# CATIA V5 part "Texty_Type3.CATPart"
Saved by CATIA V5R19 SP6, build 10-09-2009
Part number: Texty Type3
Bounding box of the stored display mesh (mm): x -20 to 20, y 0 to 0, z -20.085 to 5.085
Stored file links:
  C:\DURATEC\Texty_Type3.CATPart
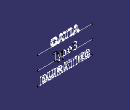
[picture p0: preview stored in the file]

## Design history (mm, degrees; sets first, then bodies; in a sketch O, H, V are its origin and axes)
Parameters
  Text.1 = "CATIA"
  Text.2 = "Type3"
  Text.3 = "DURATEC"
Set1 "Text.1"
  Line1: type PtDir, RefPoint {point type Coord, X 0, Y 0, Z 0}, Direction (1, 0, 0), Start -20, End 20
  TY3TextWarpObject1: Text "CATIA" {= Text.1}, BaseCurve Line1, Circle Start Angle 0, BasePlane zx-plane, Reference Circle Radius 0, Circle Radius 10, ParaGrapheStyleUpgraded "Center", JustificationModeUpgraded false, ParaGraphOffsetStyleUpgraded "Above the baseline", PlaneInversionUpgraded false, SlideCaliper false, ReferenceAxis "0y", CurveInversionUpgraded true, ConvergenceType "Standard", CurveType "Curve", FullTreeVisualization false, Font Type "Arial Rounded MT Bold", Font Type "Arial Rounded MT Bold", Font Type "Arial Rounded MT Bold", Font Type "Arial Rounded MT Bold", Font Type "Arial Rounded MT Bold", Font Type "Arial Rounded MT Bold", Font Family "True type font", Font Family "True type font", Font Family "True type font", Font Family "True type font", Font Family "True type font", Font Family "True type font", Case "None", Case "None", Case "None", Case "None", Case "None", Case "None", Kerning "KERN_STD", Kerning "KERN_STD", Kerning "KERN_STD", Kerning "KERN_STD", Kerning "KERN_STD", Kerning "KERN_STD", Superscript/Subscript "None", Superscript/Subscript "None", Superscript/Subscript "None", Superscript/Subscript "None", Superscript/Subscript "None", Superscript/Subscript "None", Rotation 0, Rotation 0, Rotation 0, Rotation 0, Rotation 0, Rotation 0, Extra Space 0, Extra Space 0, Extra Space 0, Extra Space 0, Extra Space 0, Extra Space 0, Text Underline Position 0, Text Underline Position 0, Text Underline Position 0, Text Underline Position 0, Text Underline Position 0, Text Underline Position 0, Position Ratio 0, Position Ratio 0, Position Ratio 0, Position Ratio 0, Position Ratio 0, Position Ratio 0, Height 5, Height 5, Height 5, Height 5, Height 5, Height 5, Width 1, Width 1, Width 1, Width 1, Width 1, Width 1, Text Italic 0, Text Italic 0, Text Italic 0, Text Italic 0, Text Italic 0, Text Italic 0
Set2 "Text.2"
  Line2: type PtDir, RefPoint {point type Coord, X 0, Y 0, Z -10}, Direction (1, 0, 0), Start -20, End 20
  TY3TextWarpObject2: Text "Type3" {= Text.2}, BaseCurve Line2, Circle Start Angle 0, BasePlane zx-plane, Reference Circle Radius 0, Circle Radius 10, ParaGrapheStyleUpgraded "Center", JustificationModeUpgraded false, ParaGraphOffsetStyleUpgraded "Above the baseline", PlaneInversionUpgraded false, SlideCaliper false, ReferenceAxis "0y", CurveInversionUpgraded true, ConvergenceType "Standard", CurveType "Curve", FullTreeVisualization false, Font Type "MECA MEDIUM 1", Font Type "MECA MEDIUM 1", Font Type "MECA MEDIUM 1", Font Type "MECA MEDIUM 1", Font Type "MECA MEDIUM 1", Font Type "MECA MEDIUM 1", Font Family "Vision numeric font", Font Family "Vision numeric font", Font Family "Vision numeric font", Font Family "Vision numeric font", Font Family "Vision numeric font", Font Family "Vision numeric font", Case "None", Case "None", Case "None", Case "None", Case "None", Case "None", Kerning "KERN_STD", Kerning "KERN_STD", Kerning "KERN_STD", Kerning "KERN_STD", Kerning "KERN_STD", Kerning "KERN_STD", Superscript/Subscript "None", Superscript/Subscript "None", Superscript/Subscript "None", Superscript/Subscript "None", Superscript/Subscript "None", Superscript/Subscript "None", Rotation 0, Rotation 0, Rotation 0, Rotation 0, Rotation 0, Rotation 0, Extra Space 0, Extra Space 0, Extra Space 0, Extra Space 0, Extra Space 0, Extra Space 0, Text Underline Position 0, Text Underline Position 0, Text Underline Position 0, Text Underline Position 0, Text Underline Position 0, Text Underline Position 0, Position Ratio 0, Position Ratio 0, Position Ratio 0, Position Ratio 0, Position Ratio 0, Position Ratio 0, Height 5, Height 5, Height 5, Height 5, Height 5, Height 5, Width 1, Width 1, Width 1, Width 1, Width 1, Width 1, Text Italic 0, Text Italic 0, Text Italic 0, Text Italic 0, Text Italic 0, Text Italic 0
Set3 "Text.3"
  Line3: type PtDir, RefPoint {point type Coord, X 0, Y 0, Z -20}, Direction (1, 0, 0), Start -20, End 20
  TY3TextWarpObject3: Text "DURATEC" {= Text.3}, BaseCurve Line3, Circle Start Angle 0, BasePlane zx-plane, Reference Circle Radius 0, Circle Radius 10, ParaGrapheStyleUpgraded "Center", JustificationModeUpgraded false, ParaGraphOffsetStyleUpgraded "Above the baseline", PlaneInversionUpgraded false, SlideCaliper false, ReferenceAxis "0y", CurveInversionUpgraded true, ConvergenceType "Standard", CurveType "Curve", FullTreeVisualization false, Font Type "Arial Black", Font Type "Arial Black", Font Type "Arial Black", Font Type "Arial Black", Font Type "Arial Black", Font Type "Arial Black", Font Type "Arial Black", Font Type "Arial Black", Font Family "True type font", Font Family "True type font", Font Family "True type font", Font Family "True type font", Font Family "True type font", Font Family "True type font", Font Family "True type font", Font Family "True type font", Case "None", Case "None", Case "None", Case "None", Case "None", Case "None", Case "None", Case "None", Kerning "KERN_STD", Kerning "KERN_STD", Kerning "KERN_STD", Kerning "KERN_STD", Kerning "KERN_STD", Kerning "KERN_STD", Kerning "KERN_STD", Kerning "KERN_STD", Superscript/Subscript "None", Superscript/Subscript "None", Superscript/Subscript "None", Superscript/Subscript "None", Superscript/Subscript "None", Superscript/Subscript "None", Superscript/Subscript "None", Superscript/Subscript "None", Rotation 0, Rotation 0, Rotation 0, Rotation 0, Rotation 0, Rotation 0, Rotation 0, Rotation 0, Extra Space 0, Extra Space 0, Extra Space 0, Extra Space 0, Extra Space 0, Extra Space 0, Extra Space 0, Extra Space 0, Text Underline Position 0, Text Underline Position 0, Text Underline Position 0, Text Underline Position 0, Text Underline Position 0, Text Underline Position 0, Text Underline Position 0, Text Underline Position 0, Position Ratio 0, Position Ratio 0, Position Ratio 0, Position Ratio 0, Position Ratio 0, Position Ratio 0, Position Ratio 0, Position Ratio 0, Height 5, Height 5, Height 5, Height 5, Height 5, Height 5, Height 5, Height 5, Width 1, Width 1, Width 1, Width 1, Width 1, Width 1, Width 1, Width 1, Text Italic 0, Text Italic 0, Text Italic 0, Text Italic 0, Text Italic 0, Text Italic 0, Text Italic 0, Text Italic 0
Body1 (main body)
